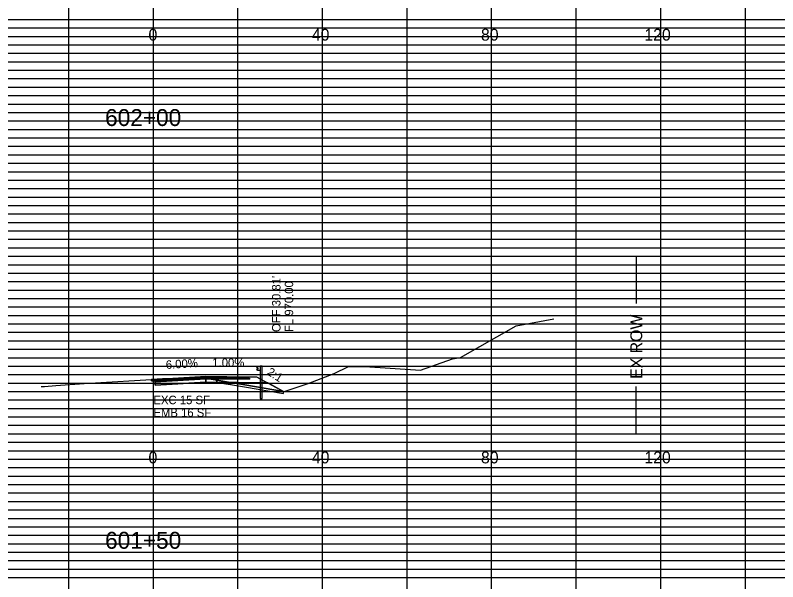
# Model space of a CAD drawing. Extents: x 2313580 to 2322968, y 282099 to 303247.
# Drawn here: x 2317959.8 to 2318140.1, y 287712.7 to 287846.7 of the extents above; entities that cross this region are included whole.
import ezdxf

# ---------------------------------------------------------------- set-up
doc = ezdxf.new("R2010")
doc.units = 0
for name, color, linetype in [('DESIGN - CENTERLINE - Proposed', 7, 'Continuous'), ('DESIGN - DRAINAGE - Text', 7, 'Continuous'), ('DESIGN - EARTHWORK - Excavation Limit Lines', 7, 'Continuous'), ('DESIGN - EARTHWORK - Shapes', 7, 'Continuous'), ('DESIGN - SCRATCH - User 1', 7, 'Continuous'), ('DESIGN - SCRATCH - User 5', 7, 'Continuous'), ('DESIGN - SHEET - Light Grid', 7, 'Continuous'), ('DESIGN - SHEET - Linework', 7, 'Continuous'), ('DESIGN - TYPICAL - Finished Grade and Subgrade', 7, 'Continuous'), ('DESIGN - TYPICAL - Finished Grade Slopes Text', 7, 'Continuous'), ('DESIGN - TYPICAL - Guardrail', 7, 'Continuous'), ('DESIGN - TYPICAL - Text', 7, 'Continuous'), ('Scratch Level', 7, 'Continuous'), ('SURVEY - GROUND - Top of Ground', 7, 'Continuous'), ('SURVEY - PROPERTY - ROW Lines Text', 7, 'Continuous')]:
    doc.layers.add(name, color=color, linetype=linetype)

# ---------------------------------------------------------------- blocks, each defined once
blk = doc.blocks.new('GRTYP')
at = {"layer": 'DESIGN - CENTERLINE - Proposed'}
for p, q in [((0.162, 0.37), (0.162, 0.37)), ((0.162, 0.37), (0.162, 0.37)), ((0.264, 0.37), (0.264, 0.37)), ((0.264, 0.37), (0.264, 0.37))]:
    blk.add_line(p, q, dxfattribs=at)
for points in [[(0.059, 0.567), (0.04, 0.563), (0.004, 0.539), (0, 0.531), (0.004, 0.523), (0.055, 0.492), (0.059, 0.484), (0.059, 0.464), (0.055, 0.456), (0.004, 0.425), (0, 0.417), (0.004, 0.409), (0.04, 0.385), (0.059, 0.382)], [(0.162, 0.374), (0.059, 0.374), (0.059, 0.574), (0.162, 0.574)], [(0.264, -0.126), (0.264, 0.574), (0.162, 0.574), (0.162, -0.075)], [(0.162, -0.075), (0.162, -0.949), (0.264, -0.949), (0.264, -0.122)]]:
    blk.add_lwpolyline(points, dxfattribs=at)

msp = doc.modelspace()

# ---------------------------------------------------------------- linework, layer by layer
at = {"layer": 'DESIGN - EARTHWORK - Shapes'}
for points in [[(2318007.46, 287759.84), (2318007.46, 287760.34), (2318005.68, 287760.63), (2318003.12, 287760.63), (2317994.67, 287760.64), (2317992.05, 287760.49), (2317992.05, 287760.39), (2317992.05, 287760.18), (2317992.89, 287760.23), (2317992.89, 287759.98), (2317992.89, 287759.15), (2318004.89, 287759.87)], [(2318010.71, 287759.81), (2318014.14, 287759.25), (2318023.29, 287757.67), (2318022.36, 287758.17), (2318019.54, 287759.71), (2318019.51, 287759.72)]]:
    msp.add_lwpolyline(points, close=True, dxfattribs=at)
at = {"layer": 'DESIGN - SCRATCH - User 1'}
msp.add_lwpolyline([(2318014.89, 287761.16), (2318016.89, 287761.14), (2318023.29, 287757.67)], dxfattribs=at)
msp.add_lwpolyline([(2318014.89, 287761.16), (2318016.89, 287761.14), (2318023.29, 287757.67)], dxfattribs=at)
msp.add_lwpolyline([(2318014.89, 287761.16), (2318016.89, 287761.14), (2318023.29, 287757.67)], dxfattribs=at)
msp.add_lwpolyline([(2318014.89, 287761.16), (2318016.89, 287761.14), (2318023.29, 287757.67)], dxfattribs=at)
at = {"layer": 'DESIGN - SCRATCH - User 5'}
for points in [[(2318010.71, 287759.81), (2318007.46, 287760.34), (2318007.46, 287759.83), (2318010.71, 287759.3)], [(2318010.71, 287759.81), (2318007.46, 287760.34), (2318007.46, 287759.83), (2318010.71, 287759.3)], [(2318010.71, 287759.3), (2318014.06, 287758.76), (2318023.28, 287757.17), (2318023.29, 287757.17), (2318023.29, 287757.67), (2318014.14, 287759.25), (2318010.71, 287759.81)], [(2318010.71, 287759.3), (2318014.06, 287758.76), (2318023.28, 287757.17), (2318023.29, 287757.17), (2318023.29, 287757.67), (2318014.14, 287759.25), (2318010.71, 287759.81)]]:
    msp.add_lwpolyline(points, close=True, dxfattribs=at)
at = {"layer": 'DESIGN - SHEET - Light Grid'}
for p, q in [((2317832.48, 287845.67), (2317992.48, 287845.67)), ((2317992.48, 287845.67), (2318152.48, 287845.67)), ((2317832.48, 287843.67), (2317992.48, 287843.67)), ((2317992.48, 287843.67), (2318152.48, 287843.67)), ((2317832.48, 287841.67), (2317992.48, 287841.67)), ((2317992.48, 287841.67), (2318152.48, 287841.67)), ((2317832.48, 287839.67), (2317992.48, 287839.67)), ((2317992.48, 287839.67), (2318152.48, 287839.67)), ((2317832.48, 287837.67), (2317992.48, 287837.67)), ((2317992.48, 287837.67), (2318152.48, 287837.67)), ((2317832.48, 287835.67), (2317992.48, 287835.67)), ((2317992.48, 287835.67), (2318152.48, 287835.67)), ((2317832.48, 287833.67), (2317992.48, 287833.67)), ((2317992.48, 287833.67), (2318152.48, 287833.67)), ((2317832.48, 287831.67), (2317992.48, 287831.67)), ((2317992.48, 287831.67), (2318152.48, 287831.67)), ((2317832.48, 287829.67), (2317992.48, 287829.67)), ((2317992.48, 287829.67), (2318152.48, 287829.67)), ((2317832.48, 287825.67), (2317992.48, 287825.67)), ((2317992.48, 287825.67), (2318152.48, 287825.67)), ((2317832.48, 287823.67), (2317992.48, 287823.67)), ((2317992.48, 287823.67), (2318152.48, 287823.67)), ((2317832.48, 287821.67), (2317992.48, 287821.67)), ((2317992.48, 287821.67), (2318152.48, 287821.67)), ((2317832.48, 287819.67), (2317992.48, 287819.67)), ((2317992.48, 287819.67), (2318152.48, 287819.67)), ((2317832.48, 287817.67), (2317992.48, 287817.67)), ((2317992.48, 287817.67), (2318152.48, 287817.67)), ((2317832.48, 287815.67), (2317992.48, 287815.67)), ((2317992.48, 287815.67), (2318152.48, 287815.67)), ((2317832.48, 287813.67), (2317992.48, 287813.67)), ((2317992.48, 287813.67), (2318152.48, 287813.67)), ((2317832.48, 287811.67), (2317992.48, 287811.67)), ((2317992.48, 287811.67), (2318152.48, 287811.67)), ((2317832.48, 287809.67), (2317992.48, 287809.67)), ((2317992.48, 287809.67), (2318152.48, 287809.67)), ((2317832.48, 287805.67), (2317992.48, 287805.67)), ((2317992.48, 287805.67), (2318152.48, 287805.67)), ((2317832.48, 287803.67), (2317992.48, 287803.67)), ((2317992.48, 287803.67), (2318152.48, 287803.67)), ((2317832.48, 287801.67), (2317992.48, 287801.67)), ((2317992.48, 287801.67), (2318152.48, 287801.67)), ((2317832.48, 287799.67), (2317992.48, 287799.67)), ((2317992.48, 287799.67), (2318152.48, 287799.67)), ((2317832.48, 287797.67), (2317992.48, 287797.67)), ((2317992.48, 287797.67), (2318152.48, 287797.67)), ((2317832.48, 287795.67), (2317992.48, 287795.67)), ((2317992.48, 287795.67), (2318152.48, 287795.67)), ((2317832.48, 287793.67), (2317992.48, 287793.67)), ((2317992.48, 287793.67), (2318152.48, 287793.67)), ((2317832.48, 287791.67), (2317992.48, 287791.67)), ((2317992.48, 287791.67), (2318152.48, 287791.67)), ((2317832.48, 287789.67), (2317992.48, 287789.67)), ((2317992.48, 287789.67), (2318152.48, 287789.67)), ((2317832.48, 287785.67), (2317992.48, 287785.67)), ((2317992.48, 287785.67), (2318152.48, 287785.67)), ((2317832.48, 287783.67), (2317992.48, 287783.67)), ((2317992.48, 287783.67), (2318152.48, 287783.67)), ((2317832.48, 287781.67), (2317992.48, 287781.67)), ((2317992.48, 287781.67), (2318152.48, 287781.67)), ((2317832.48, 287779.67), (2317992.48, 287779.67)), ((2317992.48, 287779.67), (2318152.48, 287779.67)), ((2317832.48, 287777.67), (2317992.48, 287777.67)), ((2317992.48, 287777.67), (2318152.48, 287777.67)), ((2317832.48, 287775.67), (2317992.48, 287775.67)), ((2317992.48, 287775.67), (2318152.48, 287775.67)), ((2317832.48, 287773.67), (2317992.48, 287773.67)), ((2317992.48, 287773.67), (2318152.48, 287773.67)), ((2317832.48, 287771.67), (2317992.48, 287771.67)), ((2317992.48, 287771.67), (2318152.48, 287771.67)), ((2317832.48, 287769.67), (2317992.48, 287769.67)), ((2317992.48, 287769.67), (2318152.48, 287769.67)), ((2317832.48, 287765.67), (2317992.48, 287765.67)), ((2317992.48, 287765.67), (2318152.48, 287765.67)), ((2317832.48, 287763.67), (2317992.48, 287763.67)), ((2317992.48, 287763.67), (2318152.48, 287763.67)), ((2317832.48, 287761.67), (2317992.48, 287761.67)), ((2317992.48, 287761.67), (2318152.48, 287761.67)), ((2317832.48, 287759.67), (2317992.48, 287759.67)), ((2317992.48, 287759.67), (2318152.48, 287759.67)), ((2317832.48, 287757.67), (2317992.48, 287757.67)), ((2317992.48, 287757.67), (2318152.48, 287757.67)), ((2317832.48, 287755.67), (2317992.48, 287755.67)), ((2317992.48, 287755.67), (2318152.48, 287755.67)), ((2317832.48, 287753.67), (2317992.48, 287753.67)), ((2317992.48, 287753.67), (2318152.48, 287753.67)), ((2317832.48, 287751.67), (2317992.48, 287751.67)), ((2317992.48, 287751.67), (2318152.48, 287751.67)), ((2317832.48, 287749.67), (2317992.48, 287749.67)), ((2317992.48, 287749.67), (2318152.48, 287749.67)), ((2317832.48, 287745.67), (2317992.48, 287745.67)), ((2317992.48, 287745.67), (2318152.48, 287745.67)), ((2317832.48, 287743.67), (2317992.48, 287743.67)), ((2317992.48, 287743.67), (2318152.48, 287743.67)), ((2317832.48, 287741.67), (2317992.48, 287741.67)), ((2317992.48, 287741.67), (2318152.48, 287741.67)), ((2317832.48, 287739.67), (2317992.48, 287739.67)), ((2317992.48, 287739.67), (2318152.48, 287739.67)), ((2317832.48, 287737.67), (2317992.48, 287737.67)), ((2317992.48, 287737.67), (2318152.48, 287737.67)), ((2317832.48, 287735.67), (2317992.48, 287735.67)), ((2317992.48, 287735.67), (2318152.48, 287735.67)), ((2317832.48, 287733.67), (2317992.48, 287733.67)), ((2317992.48, 287733.67), (2318152.48, 287733.67)), ((2317832.48, 287731.67), (2317992.48, 287731.67)), ((2317992.48, 287731.67), (2318152.48, 287731.67)), ((2317832.48, 287729.67), (2317992.48, 287729.67)), ((2317992.48, 287729.67), (2318152.48, 287729.67)), ((2317832.48, 287725.67), (2317992.48, 287725.67)), ((2317992.48, 287725.67), (2318152.48, 287725.67)), ((2317832.48, 287723.67), (2317992.48, 287723.67)), ((2317992.48, 287723.67), (2318152.48, 287723.67)), ((2317832.48, 287721.67), (2317992.48, 287721.67)), ((2317992.48, 287721.67), (2318152.48, 287721.67)), ((2317832.48, 287719.67), (2317992.48, 287719.67)), ((2317992.48, 287719.67), (2318152.48, 287719.67)), ((2317832.48, 287717.67), (2317992.48, 287717.67)), ((2317992.48, 287717.67), (2318152.48, 287717.67)), ((2317832.48, 287715.67), (2317992.48, 287715.67)), ((2317992.48, 287715.67), (2318152.48, 287715.67)), ((2317832.48, 287713.67), (2317992.48, 287713.67)), ((2317992.48, 287713.67), (2318152.48, 287713.67))]:
    msp.add_line(p, q, dxfattribs=at)
at = {"layer": 'DESIGN - SHEET - Linework'}
for p, q in [((2317972.48, 287587.67), (2317972.48, 288007.67)), ((2317992.48, 287587.67), (2317992.48, 288007.67)), ((2318012.48, 287587.67), (2318012.48, 288007.67)), ((2318032.48, 287587.67), (2318032.48, 288007.67)), ((2318052.48, 287587.67), (2318052.48, 288007.67)), ((2318072.48, 287587.67), (2318072.48, 288007.67)), ((2318092.48, 287587.67), (2318092.48, 288007.67)), ((2318112.48, 287587.67), (2318112.48, 288007.67)), ((2318132.48, 287587.67), (2318132.48, 288007.67)), ((2317672.48, 287827.67), (2318312.48, 287827.67)), ((2317672.48, 287807.67), (2318312.48, 287807.67)), ((2317672.48, 287787.67), (2318312.48, 287787.67)), ((2317672.48, 287767.67), (2318312.48, 287767.67)), ((2317672.48, 287747.67), (2318312.48, 287747.67)), ((2317672.48, 287727.67), (2318312.48, 287727.67))]:
    msp.add_line(p, q, dxfattribs=at)
at = {"layer": 'DESIGN - TYPICAL - Finished Grade and Subgrade'}
msp.add_lwpolyline([(2317992.05, 287760.49), (2317992.69, 287760.53), (2317992.89, 287760.54), (2317995.78, 287760.71), (2318004.89, 287761.26), (2318007.32, 287761.23), (2318014.89, 287761.16), (2318015.38, 287761.15), (2318016.89, 287761.14), (2318018.85, 287760.07), (2318019.51, 287759.72), (2318022.36, 287758.17), (2318023.29, 287757.67)], dxfattribs=at)
for points in [[(2317992.89, 287760.54), (2317992.05, 287760.49), (2317992.05, 287760.39), (2317992.89, 287760.43)], [(2317992.89, 287760.54), (2317992.05, 287760.49), (2317992.05, 287760.39), (2317992.89, 287760.43)], [(2317992.89, 287760.43), (2317992.89, 287760.23), (2317992.05, 287760.18), (2317992.05, 287760.39)], [(2317992.89, 287760.54), (2318004.89, 287761.26), (2318004.89, 287761.16), (2317992.89, 287760.43)], [(2317992.89, 287760.43), (2318004.89, 287761.16), (2318004.89, 287760.95), (2317992.89, 287760.23)], [(2317992.89, 287760.23), (2318004.89, 287760.95), (2318004.89, 287760.7), (2317992.89, 287759.98)], [(2317992.89, 287759.98), (2318004.89, 287760.7), (2318004.89, 287759.87), (2317992.89, 287759.15)], [(2318004.89, 287761.26), (2318014.89, 287761.16), (2318014.89, 287761.06), (2318004.89, 287761.16)], [(2318004.89, 287760.7), (2318015.2, 287760.6), (2318015.2, 287760.85), (2318015, 287760.86), (2318015, 287761.06), (2318014.89, 287761.06), (2318014.89, 287761.16), (2318016.89, 287761.14), (2318018.85, 287760.07), (2318019.51, 287759.72), (2318004.89, 287759.87)], [(2318004.89, 287761.16), (2318015, 287761.06), (2318015, 287760.86), (2318004.89, 287760.95)], [(2318004.89, 287760.95), (2318015.2, 287760.85), (2318015.2, 287760.6), (2318004.89, 287760.7)]]:
    msp.add_lwpolyline(points, close=True, dxfattribs=at)
at = {"layer": 'Scratch Level'}
for points in [[(2318007.46, 287759.84), (2318007.46, 287760.34), (2318005.68, 287760.63), (2318003.12, 287760.63), (2317994.67, 287760.64), (2317992.05, 287760.49), (2317992.05, 287760.39), (2317992.05, 287760.18), (2317992.89, 287760.23), (2317992.89, 287759.98), (2317992.89, 287759.15), (2318004.89, 287759.87)], [(2318010.71, 287759.81), (2318014.14, 287759.25), (2318023.29, 287757.67), (2318022.36, 287758.17), (2318019.54, 287759.71), (2318019.51, 287759.72)]]:
    msp.add_lwpolyline(points, close=True, dxfattribs=at)
at = {"layer": 'SURVEY - GROUND - Top of Ground'}
msp.add_lwpolyline([(2317965.93, 287758.84), (2317966.16, 287758.83), (2317966.71, 287758.88), (2317969.38, 287759.12), (2317976.11, 287759.54), (2317994.67, 287760.64), (2318003.12, 287760.63), (2318005.68, 287760.63), (2318014.14, 287759.25), (2318023.29, 287757.67), (2318023.62, 287757.72), (2318029.09, 287759.6), (2318035.21, 287761.96), (2318038.6, 287763.55), (2318042.47, 287763.62), (2318055.63, 287762.71), (2318063.21, 287765.39), (2318065.15, 287765.68), (2318078.3, 287773.21), (2318087.22, 287774.85)], dxfattribs=at)
at = {"layer": 'SURVEY - PROPERTY - ROW Lines Text'}
for p, q in [((2318106.68, 287789.67), (2318106.68, 287778.47)), ((2318106.68, 287747.67), (2318106.68, 287758.87))]:
    msp.add_line(p, q, dxfattribs=at)

# ---------------------------------------------------------------- block references
at = {"layer": 'DESIGN - TYPICAL - Guardrail', "xscale": 5, "yscale": 5}
msp.add_blockref('GRTYP', (2318016.89, 287760.76), dxfattribs=at)

# ---------------------------------------------------------------- texts
at = {"layer": 'DESIGN - DRAINAGE - Text'}
for s, p in [("OFF 30.81'", (2318022.54, 287771.73)), ('FL 970.00', (2318025.54, 287771.73))]:
    msp.add_text(s, height=2, rotation=90, dxfattribs=at).set_placement(p)
at = {"layer": 'DESIGN - EARTHWORK - Excavation Limit Lines'}
for s, p in [('EXC 15 SF', (2317992.48, 287754.67)), ('EMB 16 SF', (2317992.48, 287751.67))]:
    msp.add_text(s, height=2, dxfattribs=at).set_placement(p)
at = {"layer": 'DESIGN - TYPICAL - Finished Grade Slopes Text'}
for s, rotation, p in [('1.00%', 359.4276, (2318006.4, 287763.54)), ('6.00%', 3.4342, (2317995.48, 287763)), ('2:1', 327.8549, (2318019.15, 287761.8))]:
    msp.add_text(s, height=2, rotation=rotation, dxfattribs=at).set_placement(p)
at = {"layer": 'DESIGN - TYPICAL - Text'}
for s, height, p in [('0', 2.8, (2317991.32, 287840.67)), ('40', 2.8, (2318029.95, 287840.67)), ('80', 2.8, (2318069.95, 287840.67)), ('120', 2.8, (2318108.59, 287840.67)), ('602+00', 4, (2317981.06, 287820.47)), ('0', 2.8, (2317991.32, 287740.67)), ('40', 2.8, (2318029.95, 287740.67)), ('80', 2.8, (2318069.95, 287740.67)), ('120', 2.8, (2318108.59, 287740.67)), ('601+50', 4, (2317981.06, 287720.47))]:
    msp.add_text(s, height=height, dxfattribs=at).set_placement(p)
at = {"layer": 'SURVEY - PROPERTY - ROW Lines Text'}
msp.add_text('EX ROW', height=2.8, rotation=90, dxfattribs=at).set_placement((2318108.08, 287760.67))

doc.saveas('drawing.dxf')
